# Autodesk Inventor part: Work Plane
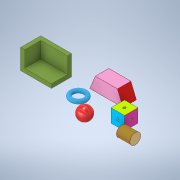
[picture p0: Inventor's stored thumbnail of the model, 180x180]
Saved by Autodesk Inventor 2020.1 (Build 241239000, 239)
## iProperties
Created: 2018-06
Part Number: Work Plane
Material: Generic
Document SubType Name: Modeling
Designer: Power User
Density: 1 g/cm^3
Appearance: Light Red
Author: Power User
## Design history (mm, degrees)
sketch "Sketch1"
  geometry: L1 (0, 0)-(50, 0); L2 (50, 0)-(50, -50); L3 (50, -50)-(0, -50); L4 (0, -50)-(0, 0); 1 further point
  constraints: 8 end point, 2 parallel, 1 coincident, 1 horizontal, 1 perpendicular
  dimensions: "d0" = 50 distance of L1.end L2.end; "d1" = 50 distance of L2.end L3.end; "d53" = 0 distance from line of point (0, 0) L4
extrude "Extrusion1" new body sketch "Sketch1" distance "d2" = 50; taper "d3" = 0 deg
workplane "Work Plane1"
sketch "Sketch2"
  geometry: L1 (0, 50)-(50, 50) reference; L2 (50, 0)-(50, 50) reference; C1 r 20 at (-30, 25); 3 further points
  constraints: 2 midpoint, 1 centre point, 1 horizontal alignment
  dimensions: "d5" = 40 diameter of C1; "d54" = 30 horizontal distance of C1.centre point (0, 0)
extrude "Extrusion2" new body sketch "Sketch2" distance "d6" = 50; taper "d7" = 0 deg
sketch "Sketch3"
  geometry: L1 (-172.16, 49.98)-(-172.16, 11.482); C1 r 7.5 at (-197.16, 26.587); 1 further point
  constraints: 2 end point, 1 centre point, 1 vertical
  dimensions: "d8" = 15 diameter of C1; "d9" = 50 diameter of C1.centre L1
revolve "Revolution1" sketch "Sketch3" stored, may be unused: angle "d10" = 90 deg
workplane "Work Plane2"
sketch "Sketch4"
  geometry: L1 (-98.807, 58.325)-(-98.807, 8.325); A1 r 25 centre (-98.807, 33.325) between (-98.807, 58.325) and (-98.807, 8.325); 1 further point
  constraints: 2 end point, 2 point on circle, 1 centre point, 1 vertical
  dimensions: "d12" = 50 diameter of A1
revolve "Revolution2" sketch "Sketch4" stored, may be unused: angle "d13" = 90 deg
workplane "Work Plane3"
sketch "Sketch5"
  geometry: L1 (-192.037, 9.98)-(-171.326, 59.98); L2 (-171.326, 59.98)-(-89.041, 59.98); L3 (-89.041, 59.98)-(-68.33, 9.98); L4 (-68.33, 9.98)-(-192.037, 9.98); L5 (-130.184, 59.98)-(-130.184, 9.98); 1 further point
  constraints: 10 end point, 2 midpoint, 1 horizontal, 1 parallel, 1 perpendicular, 1 other
  dimensions: "d15" = 50 distance between parallel lines of L4 L2; "d16" = 45 deg angle of L3 L1
extrude "Extrusion3" new body sketch "Sketch5" stored distance "d17" = 50; taper "d18" = 0 deg
sketch "Sketch6"
  geometry: L1 (15, 35)-(35, 35); L2 (35, 35)-(35, 15); L3 (35, 15)-(15, 15); L4 (15, 15)-(15, 35); L5 (0, 50)-(50, 50) reference; L6 (0, 0)-(0, 50) reference; 5 further points
  constraints: 4 midpoint, 1 horizontal alignment, 1 vertical alignment, 2 other
  dimensions: "d19" = 20 distance of L1.start L1.end; "d20" = 20 distance of L1.end L2.end
emboss "Emboss1" sketch "Sketch6" dims "d1" = 50, "d12" = 50, "d21" = 0.2, "d22" = 0
sketch "Sketch7"
  geometry: L1 (-35, 35)-(-15, 35); L2 (-15, 35)-(-15, 15); L3 (-15, 15)-(-35, 15); L4 (-35, 15)-(-35, 35); L5 (0, 50)-(-50, 50) reference; L6 (-50, 50)-(-50, 0) reference; 5 further points
  constraints: 4 midpoint, 1 horizontal alignment, 1 vertical alignment, 2 other
  dimensions: "d23" = 20 distance of L1.start L1.end; "d24" = 20 distance of L3.end L1.start
emboss "Emboss2" sketch "Sketch7" dims "d1" = 50, "d12" = 50, "d25" = 0.2, "d26" = 0
sketch "Sketch8"
  geometry: L1 (15, 35)-(35, 35); L2 (35, 35)-(35, 15); L3 (35, 15)-(15, 15); L4 (15, 15)-(15, 35); L5 (0, 0)-(0, 50) reference; L6 (0, 50)-(50, 50) reference; 4 further points
  constraints: 4 midpoint, 1 horizontal alignment, 1 vertical alignment, 2 other
  dimensions: "d27" = 20 distance of L1.start L1.end; "d28" = 20 distance of L3.end L1.start
emboss "Emboss3" sketch "Sketch8" dims "d1" = 50, "d12" = 50, "d29" = 0.2, "d30" = 0
sketch "Sketch9"
  geometry: L1 (-11.219, -35.018)-(-35.694, -35.018); L2 (-35.694, -35.018)-(-35.694, -14.982); L3 (-35.694, -14.982)-(-11.219, -14.982); L4 (-11.219, -14.982)-(-11.219, -35.018); L5 (0, -50)-(0, 0) reference; 4 further points
  constraints: 3 midpoint, 1 horizontal alignment, 1 vertical alignment, 2 other
emboss "Emboss4" sketch "Sketch9" dims "d1" = 50, "d12" = 50, "d31" = 0.2, "d32" = 0
sketch "Sketch10"
  geometry: L1 (15, 35)-(35, 35); L2 (35, 35)-(35, 15); L3 (35, 15)-(15, 15); L4 (15, 15)-(15, 35); L5 (0, 50)-(50, 50) reference; L6 (0, 0)-(0, 50) reference; 5 further points
  constraints: 4 midpoint, 1 horizontal alignment, 1 vertical alignment, 2 other
  dimensions: "d33" = 20 distance of L1.start L1.end; "d34" = 20 distance of L3.end L1.start
emboss "Emboss5" sketch "Sketch10" dims "d1" = 50, "d12" = 50, "d35" = 0.2, "d36" = 0
sketch "Sketch11"
  geometry: L1 (15, 35)-(35, 35); L2 (35, 35)-(35, 15); L3 (35, 15)-(15, 15); L4 (15, 15)-(15, 35); L5 (0, 0)-(0, 50) reference; L6 (0, 50)-(50, 50) reference; 4 further points
  constraints: 4 midpoint, 1 horizontal alignment, 1 vertical alignment, 2 other
  dimensions: "d37" = 20 distance of L1.start L1.end; "d38" = 20 distance of L1.end L2.end
emboss "Emboss6" sketch "Sketch11" dims "d1" = 50, "d12" = 50, "d39" = 0.2, "d40" = 0
sketch "Sketch12"
  geometry: L1 (118.439, 97.246)-(43.439, 97.246); L2 (43.439, 97.246)-(43.439, 172.246); L3 (43.439, 172.246)-(58.439, 172.246); L4 (58.439, 172.246)-(58.439, 112.246); L5 (58.439, 112.246)-(118.439, 112.246); L6 (118.439, 112.246)-(118.439, 97.246); 1 further point
  constraints: 12 end point, 4 perpendicular, 1 horizontal, 1 vertical
  dimensions: "d41" = 75 distance of L1.start L1.end; "d42" = 75 distance of L1.end L2.end (= d41); "d43" = 15 distance of L5.end L1.start; "d44" = 15 distance of L2.end L3.end (= d43)
extrude "Extrusion4" new body sketch "Sketch12" stored distance "d45" = 100; taper "d46" = 0 deg
sketch "Sketch13"
  geometry: L1 (97.246, 118.439)-(97.246, 43.439) reference; L2 (97.246, 43.439)-(172.246, 43.439) reference; L3 (172.246, 43.439)-(97.246, 43.439) reference; L4 (172.246, 118.439)-(97.246, 118.439); L5 (97.246, 118.439)-(97.246, 43.439); L6 (97.246, 43.439)-(172.246, 43.439); L7 (172.246, 43.439)-(172.246, 118.439); L8 (172.246, 118.439)-(97.246, 43.439); L9 (97.246, 118.439)-(172.246, 43.439); 2 further points
  constraints: 12 end point, 2 equal length, 2 midpoint, 2 parallel, 1 horizontal, 1 perpendicular
extrude "Extrusion5" join sketch "Sketch13" distance "d47" = 15; taper "d48" = 0 deg
feature "Move Body1"
node "Cube"
node "Cylinder"
node "Ring"
node "Sphere"
node "Trapezoid"
node "Solid"
other parameters: "d14" = -87.5
